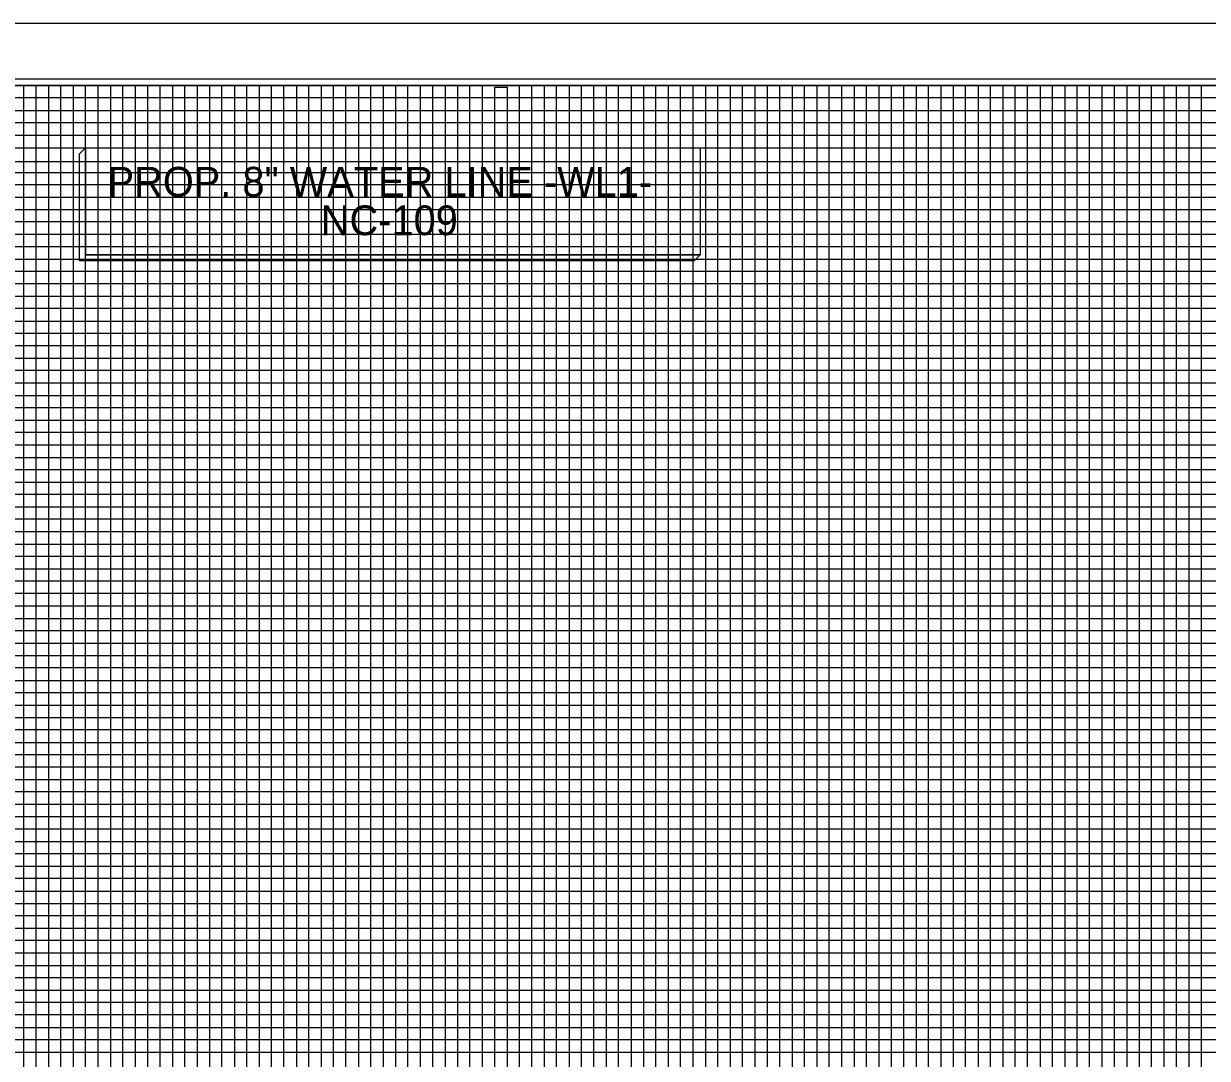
# Model space of a CAD drawing. Extents: x 3814791 to 3815465, y 1224203 to 1224643.
# Drawn here: x 3815088.1 to 3815279.1, y 1224476.2 to 1224643.2 of the extents above; entities that cross this region are included whole.
import ezdxf

# ---------------------------------------------------------------- set-up
doc = ezdxf.new("R2010")
doc.units = 0
for name, color, linetype in [('COGO Default Chain', 7, 'Continuous'), ('Exist Roads EOP', 7, 'Continuous'), ('Pattern 49', 7, 'Continuous'), ('Scratch_Level_1', 7, 'Continuous')]:
    doc.layers.add(name, color=color, linetype=linetype)

msp = doc.modelspace()

# ---------------------------------------------------------------- linework, layer by layer
at = {"layer": 'COGO Default Chain'}
for p, q in [((3815097.11, 1224622.19), (3815098.11, 1224623.19)), ((3815197.29, 1224605.91), (3815196.29, 1224604.91)), ((3815197.29, 1224605.91), (3815196.29, 1224604.91))]:
    msp.add_line(p, q, dxfattribs=at)
for points in [[(3815196.29, 1224604.91), (3815097.11, 1224604.91), (3815097.11, 1224622.19)], [(3815098.11, 1224623.19), (3815098.11, 1224605.91), (3815197.29, 1224605.91)]]:
    msp.add_lwpolyline(points, dxfattribs=at)
msp.add_lwpolyline([(3815098.11, 1224623.19), (3815197.29, 1224623.19), (3815197.29, 1224605.91), (3815098.11, 1224605.91)], close=True, dxfattribs=at)
at = {"layer": 'Exist Roads EOP'}
for p, q in [((3814878.11, 1224633.21), (3815378.11, 1224633.21)), ((3815438.11, 1224561.21), (3814878.11, 1224561.21)), ((3814878.11, 1224559.21), (3815438.11, 1224559.21)), ((3815438.11, 1224551.21), (3814878.11, 1224551.21))]:
    msp.add_line(p, q, dxfattribs=at)
for points in [[(3815458.11, 1224633.21), (3814858.11, 1224633.21), (3814858.11, 1224213.21), (3815458.11, 1224213.21)], [(3814878.11, 1224633.21), (3814878.11, 1224223.21), (3815438.11, 1224223.21), (3815438.11, 1224578.19), (3815378.11, 1224578.19), (3815378.11, 1224633.21)]]:
    msp.add_lwpolyline(points, close=True, dxfattribs=at)
for points in [[(3815088.11, 1224223.21), (3815088.11, 1224633.21), (3815108.11, 1224633.21), (3815108.11, 1224223.21)], [(3815090.11, 1224223.21), (3815090.11, 1224633.21), (3815092.11, 1224633.21), (3815092.11, 1224223.21)], [(3815094.11, 1224223.21), (3815094.11, 1224633.21), (3815096.11, 1224633.21), (3815096.11, 1224223.21)], [(3815098.11, 1224223.21), (3815098.11, 1224633.21), (3815118.11, 1224633.21), (3815118.11, 1224223.21)], [(3815100.11, 1224223.21), (3815100.11, 1224633.21), (3815102.11, 1224633.21), (3815102.11, 1224223.21)], [(3815104.11, 1224223.21), (3815104.11, 1224633.21), (3815106.11, 1224633.21), (3815106.11, 1224223.21)], [(3815110.11, 1224223.21), (3815110.11, 1224633.21), (3815112.11, 1224633.21), (3815112.11, 1224223.21)], [(3815114.11, 1224223.21), (3815114.11, 1224633.21), (3815116.11, 1224633.21), (3815116.11, 1224223.21)], [(3815120.11, 1224223.21), (3815120.11, 1224633.21), (3815122.11, 1224633.21), (3815122.11, 1224223.21)], [(3815124.11, 1224223.21), (3815124.11, 1224633.21), (3815126.11, 1224633.21), (3815126.11, 1224223.21)], [(3815128.11, 1224223.21), (3815128.11, 1224633.21), (3815148.11, 1224633.21), (3815148.11, 1224223.21)], [(3815130.11, 1224223.21), (3815130.11, 1224633.21), (3815132.11, 1224633.21), (3815132.11, 1224223.21)], [(3815134.11, 1224223.21), (3815134.11, 1224633.21), (3815136.11, 1224633.21), (3815136.11, 1224223.21)], [(3815138.11, 1224223.21), (3815138.11, 1224633.21), (3815158.11, 1224633.21), (3815158.11, 1224223.21)], [(3815140.11, 1224223.21), (3815140.11, 1224633.21), (3815142.11, 1224633.21), (3815142.11, 1224223.21)], [(3815144.11, 1224223.21), (3815144.11, 1224633.21), (3815146.11, 1224633.21), (3815146.11, 1224223.21)], [(3815150.11, 1224223.21), (3815150.11, 1224633.21), (3815152.11, 1224633.21), (3815152.11, 1224223.21)], [(3815154.11, 1224223.21), (3815154.11, 1224633.21), (3815156.11, 1224633.21), (3815156.11, 1224223.21)], [(3815160.11, 1224223.21), (3815160.11, 1224633.21), (3815162.11, 1224633.21), (3815162.11, 1224223.21)], [(3815164.11, 1224223.21), (3815164.11, 1224632.97), (3815166.11, 1224632.97), (3815166.11, 1224223.21)], [(3815168.11, 1224223.21), (3815168.11, 1224633.21), (3815188.11, 1224633.21), (3815188.11, 1224223.21)], [(3815170.11, 1224223.21), (3815170.11, 1224633.21), (3815172.11, 1224633.21), (3815172.11, 1224223.21)], [(3815174.11, 1224223.21), (3815174.11, 1224633.21), (3815176.11, 1224633.21), (3815176.11, 1224223.21)], [(3815178.11, 1224223.21), (3815178.11, 1224633.21), (3815198.11, 1224633.21), (3815198.11, 1224223.21)], [(3815180.11, 1224223.21), (3815180.11, 1224633.21), (3815182.11, 1224633.21), (3815182.11, 1224223.21)], [(3815184.11, 1224223.21), (3815184.11, 1224633.21), (3815186.11, 1224633.21), (3815186.11, 1224223.21)], [(3815190.11, 1224223.21), (3815190.11, 1224633.21), (3815192.11, 1224633.21), (3815192.11, 1224223.21)], [(3815194.11, 1224223.21), (3815194.11, 1224633.21), (3815196.11, 1224633.21), (3815196.11, 1224223.21)], [(3815200.11, 1224223.21), (3815200.11, 1224633.21), (3815202.11, 1224633.21), (3815202.11, 1224223.21)], [(3815204.11, 1224223.21), (3815204.11, 1224633.21), (3815206.11, 1224633.21), (3815206.11, 1224223.21)], [(3815208.11, 1224223.21), (3815208.11, 1224633.21), (3815228.11, 1224633.21), (3815228.11, 1224223.21)], [(3815210.11, 1224223.21), (3815210.11, 1224633.21), (3815212.11, 1224633.21), (3815212.11, 1224223.21)], [(3815214.11, 1224223.21), (3815214.11, 1224633.21), (3815216.11, 1224633.21), (3815216.11, 1224223.21)], [(3815218.11, 1224223.21), (3815218.11, 1224633.21), (3815238.11, 1224633.21), (3815238.11, 1224223.21)], [(3815220.11, 1224223.21), (3815220.11, 1224633.21), (3815222.11, 1224633.21), (3815222.11, 1224223.21)], [(3815224.11, 1224223.21), (3815224.11, 1224633.21), (3815226.11, 1224633.21), (3815226.11, 1224223.21)], [(3815230.11, 1224223.21), (3815230.11, 1224633.21), (3815232.11, 1224633.21), (3815232.11, 1224223.21)], [(3815234.11, 1224223.21), (3815234.11, 1224633.21), (3815236.11, 1224633.21), (3815236.11, 1224223.21)], [(3815240.11, 1224223.21), (3815240.11, 1224633.21), (3815242.11, 1224633.21), (3815242.11, 1224223.21)], [(3815244.11, 1224223.21), (3815244.11, 1224633.21), (3815246.11, 1224633.21), (3815246.11, 1224223.21)], [(3815248.11, 1224223.21), (3815248.11, 1224633.21), (3815268.11, 1224633.21), (3815268.11, 1224223.21)], [(3815250.11, 1224223.21), (3815250.11, 1224633.21), (3815252.11, 1224633.21), (3815252.11, 1224223.21)], [(3815254.11, 1224223.21), (3815254.11, 1224633.21), (3815256.11, 1224633.21), (3815256.11, 1224223.21)], [(3815258.11, 1224223.21), (3815258.11, 1224633.21), (3815278.11, 1224633.21), (3815278.11, 1224223.21)], [(3815260.11, 1224223.21), (3815260.11, 1224633.21), (3815262.11, 1224633.21), (3815262.11, 1224223.21)], [(3815264.11, 1224223.21), (3815264.11, 1224633.21), (3815266.11, 1224633.21), (3815266.11, 1224223.21)], [(3815270.11, 1224223.21), (3815270.11, 1224633.21), (3815272.11, 1224633.21), (3815272.11, 1224223.21)], [(3815274.11, 1224223.21), (3815274.11, 1224633.21), (3815276.11, 1224633.21), (3815276.11, 1224223.21)], [(3815378.09, 1224631.21), (3814878.11, 1224631.21), (3814878.11, 1224629.21), (3815378.09, 1224629.21)], [(3815378.09, 1224627.21), (3814878.11, 1224627.21), (3814878.11, 1224625.21), (3815378.09, 1224625.21)], [(3815378.09, 1224603.21), (3814858.15, 1224603.21), (3814858.15, 1224623.19), (3815378.09, 1224623.19)], [(3815378.09, 1224620.91), (3814878.11, 1224620.91), (3814878.11, 1224619.21), (3815378.09, 1224619.21)], [(3815378.09, 1224617.21), (3814878.11, 1224617.21), (3814878.11, 1224615.21), (3815378.09, 1224615.21)], [(3814858.11, 1224613.21), (3815378.09, 1224613.21)], [(3815378.09, 1224611.21), (3814878.11, 1224611.21), (3814878.11, 1224609.21), (3815378.09, 1224609.21)], [(3815378.11, 1224607.21), (3814878.11, 1224607.21), (3814878.11, 1224605.21), (3815378.09, 1224605.21)], [(3815378.09, 1224601.21), (3814878.11, 1224601.21), (3814878.11, 1224599.21), (3815378.09, 1224599.21)], [(3815378.09, 1224597.21), (3814878.11, 1224597.21), (3814878.11, 1224595.21), (3815378.09, 1224595.21)], [(3815378.09, 1224593.21), (3814858.11, 1224593.21), (3814858.11, 1224573.19), (3815458.11, 1224573.19)], [(3815378.09, 1224591.21), (3814878.11, 1224591.21), (3814878.11, 1224589.21), (3815378.09, 1224589.21)], [(3815378.09, 1224587.21), (3814878.11, 1224587.21), (3814878.11, 1224585.21), (3815378.09, 1224585.21)], [(3815458.11, 1224563.21), (3814858.11, 1224563.21), (3814858.11, 1224583.21), (3815378.09, 1224583.21)], [(3815378.09, 1224581.21), (3814878.11, 1224581.21), (3814878.11, 1224579.21), (3815378.09, 1224579.21)], [(3815438.11, 1224577.21), (3814878.11, 1224577.21), (3814878.11, 1224577.21), (3814878.11, 1224569.21), (3815458.11, 1224569.21)], [(3814878.11, 1224575.21), (3815378.11, 1224575.21)], [(3815438.11, 1224571.21), (3814878.11, 1224571.21)], [(3815438.11, 1224567.21), (3814878.11, 1224567.21), (3814878.11, 1224565.21), (3815438.11, 1224565.21)], [(3815438.11, 1224557.21), (3814878.11, 1224557.21), (3814878.11, 1224555.21), (3815438.11, 1224555.21)], [(3815458.11, 1224553.21), (3814858.11, 1224553.21), (3814858.11, 1224533.21), (3815458.11, 1224533.21)], [(3815438.11, 1224549.21), (3814878.11, 1224549.21), (3814878.11, 1224547.21), (3815438.11, 1224547.21)], [(3815438.11, 1224545.21), (3814878.11, 1224545.21)], [(3815458.11, 1224523.21), (3814858.11, 1224523.21), (3814858.11, 1224543.21), (3815458.11, 1224543.21)], [(3814878.11, 1224541.21), (3815438.11, 1224541.21)], [(3815438.11, 1224539.21), (3814878.11, 1224539.21), (3814878.11, 1224537.21), (3815438.11, 1224537.21)], [(3815438.11, 1224535.21), (3814878.11, 1224535.21), (3814878.11, 1224531.21), (3815438.11, 1224531.21)], [(3815438.11, 1224529.21), (3814878.11, 1224529.21), (3814878.11, 1224527.21), (3815438.11, 1224527.21)], [(3815438.11, 1224525.21), (3814878.11, 1224525.21), (3814878.11, 1224521.21), (3815438.11, 1224521.21)], [(3815438.11, 1224519.21), (3814878.11, 1224519.21), (3814878.11, 1224517.21), (3815438.11, 1224517.21)], [(3815438.11, 1224515.21), (3814878.11, 1224515.21), (3814878.11, 1224511.21), (3815438.11, 1224511.21)], [(3815458.11, 1224513.21), (3814858.11, 1224513.21), (3814858.11, 1224493.21), (3815458.11, 1224493.21)], [(3815438.11, 1224509.21), (3814878.11, 1224509.21), (3814878.11, 1224507.21), (3815438.11, 1224507.21)], [(3815438.11, 1224505.21), (3814878.11, 1224505.21), (3814878.11, 1224501.21), (3815438.11, 1224501.21)], [(3815458.11, 1224483.21), (3814858.11, 1224483.21), (3814858.11, 1224503.21), (3815458.11, 1224503.21)], [(3815438.11, 1224499.21), (3814878.11, 1224499.21), (3814878.11, 1224497.21), (3815438.11, 1224497.21)], [(3815438.11, 1224495.21), (3814878.11, 1224495.21), (3814878.11, 1224491.21), (3815438.11, 1224491.21)], [(3815438.11, 1224489.21), (3814878.11, 1224489.21), (3814878.11, 1224487.21), (3815438.11, 1224487.21)], [(3815438.11, 1224485.21), (3814878.11, 1224485.21), (3814878.11, 1224481.21), (3815438.11, 1224481.21)], [(3815438.11, 1224479.21), (3814878.11, 1224479.21), (3814878.11, 1224477.21), (3815438.11, 1224477.21)]]:
    msp.add_lwpolyline(points, dxfattribs=at)
at = {"layer": 'Pattern 49'}
msp.add_lwpolyline([(3815463.11, 1224634.23), (3814796.51, 1224634.23), (3814796.51, 1224212.19), (3815463.11, 1224212.19)], close=True, dxfattribs=at)
at = {"layer": 'Scratch_Level_1'}
msp.add_lwpolyline([(3815464.91, 1224643.21), (3814791.31, 1224643.21), (3814791.31, 1224203.21), (3815464.91, 1224203.21)], close=True, dxfattribs=at)

# ---------------------------------------------------------------- texts
at = {"layer": 'COGO Default Chain'}
for s, p in [('PROP. 8" WATER LINE -WL1-', (3815101.65, 1224615.29)), ('NC-109', (3815136.05, 1224609.07))]:
    msp.add_text(s, height=4.8, rotation=360, dxfattribs=at).set_placement(p)

doc.saveas('drawing.dxf')
